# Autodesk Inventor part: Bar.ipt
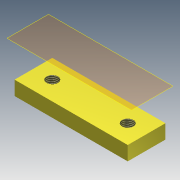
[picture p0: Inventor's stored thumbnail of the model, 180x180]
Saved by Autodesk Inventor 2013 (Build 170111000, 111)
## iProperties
Created: 2005-05
Part Number: Bar.ipt
Material: Steel, Mild
Document SubType Name: Modeling
Designer: elarisa
Manufacturer: Standard
Standards Organization: Custom
Density: 7.86 g/cm^3
Mass: 539.252 g
Surface Area: 150.786 cm^2
Volume: 68.6071 cm^3
Author: elarisa
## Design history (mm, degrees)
sketch "Эскиз1"
  geometry: L1 (-13.2, 20.6)-(106.8, 20.6); L2 (106.8, 20.6)-(106.8, -19.4); L3 (106.8, -19.4)-(-13.2, -19.4); L4 (-13.2, -19.4)-(-13.2, 20.6); C1 r 6 at (6.8, 0.6); C2 r 6 at (86.8, 0.6)
  constraints: 8 end point, 2 centre point, 2 parallel, 1 horizontal, 1 perpendicular
  dimensions: "d0" = 40 distance of L3.end L1.start; "d1" = 120 distance of L1.start L1.end; "d2" = 12 diameter of C1; "d3" = 12 diameter of C2; "d4" = 20 distance from line of L3 C1.centre; "d5" = 20 distance from line of L4 C1.centre; "d6" = 20 distance from line of L2 C2.centre; "d7" = 0 vertical distance of C2.centre C1.centre
extrude "Выдавливание1" new body sketch "Эскиз1" distance "d8" = 15; taper "d9" = 0 deg
feature "Резьба1" dims "d10" = 10, "d11" = 0
feature "Резьба2" dims "d12" = 10, "d13" = 0
node "РабПлоскость1"
body "Solid1"
other parameters: "d14" = 36
